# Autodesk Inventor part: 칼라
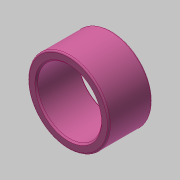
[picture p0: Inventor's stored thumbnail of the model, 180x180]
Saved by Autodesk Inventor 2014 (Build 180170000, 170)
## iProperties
Created: 2019-05
Part Number: 칼라
Material: 스테인리스강
Document SubType Name: Modeling
Designer: mduedu
Density: 1 g/cm^3
Appearance: Pink
Author: mduedu
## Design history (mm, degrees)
sketch "스케치1"
  geometry: C1 r 11 at (0, 0); C2 r 14 at (0, 0); 1 further point
  constraints: 2 centre point, 2 coincident
  dimensions: "d0" = 22 diameter of C1; "d1" = 28 diameter of C2
extrude "돌출1" new body sketch "스케치1" distance "d2" = 15; taper "d3" = 0 deg
fillet "모깎기1" dims "d4" = 0.5
chamfer "모따기1" distance "d5" = 0.5; stored, may be unused: second distance "d6" = 2, angle "d7" = 45 deg
node "솔리드1"
